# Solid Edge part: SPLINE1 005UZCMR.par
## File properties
Title: Feature: Straight-Sided Splines 8x32x36
Template: Normal.par
Last saved by: Dan
Revision: 8
Application: Solid Edge
Project Name: Piston Pump P52
Mscpartversion: 2
ProtocolId (internal): P00040720102146988
Protocol (internal): P00040720102146988<@PID>[Data]<@EL>P=15{kW<@EL>n=3000{rpm<@EL>Mk=47.747{Nm<@EL>t=0{ND<@EL>Scale=3{ND<@EL>l=27{mm<@EL>z=8{ND<@EL>d=32{mm<@EL>d1=36{mm<@EL>b=6{mm<@EL>f=0.4{mm<@EL>r=0.3{mm<@EL>d_1=30.4{mm<@EL>pom=0{ND<@EL>Mat=User{ND<@EL>Pd=30{MPa<@EL>Ks=0.75{ND<@EL>Pv=14.448{MPa<@EL>lmin=13{mm<@EL>Ready=0{ND<@EL>[Synchronize]<@EL>ChangedVars=<@EL>[Calc]<@EL>CalcName=Spline1<@EL>Optim=1<@EL>WizardMode=2<@EL>[BaseView]<@EL>OnTop=0<@EL>Left=298<@EL>Top=205<@EL>W2=350<@EL>H2=568<@EL>BaseView=1<@EL>EnableUpdate=<@EL>Calculated=1<@EL>InOpt=0<@EL>NewProt=P00040720102146988<@EL>UpdateAll=0<@EL>[View]<@EL>View=MODEL_FM<@EL>Description=Param. feature - shaft<@EL>VISIBLED=1<@EL>Data=(setq _data (list "6x23x26" "8" "32" "36" "0.4" "6" "0.3" "27" "30.4" "0" "0"))<@EL>Driver=C:/PROGRAM FILES/SOLID EDGE V15/HANDBOOK/DATA/DRV/SPLINE1.LSP<@EL>[Files]<@EL>DataFile=SpiData|SPLINE1<@EL>[Object]<@EL>ProtID=<@EL>Description=Straight-Sided Splining Component Wizard<@EL>Object=SPLINE1<@EL>[Main]<@EL>DataFile=SpiData|SPLINE1<@EL>View=MODEL_FM<@EL>Standard=DIN<@EL>PartKey=6x23x26<@EL>[Acad]<@EL>Recalc=0<@EL>SmartPart=1<@EL>Update=0<@EL>ReallySmartPart=1<@EL>Loop=0<@EL>Optim=0<@EL>[Globals]<@EL>Standard=DIN<@EL>Language=CZ<@EL>OldOwnerHwnd=460760<@EL>OwnerHwnd=1115242<@EL>Scale=1.0<@EL>Path=C:\PROGRAM FILES\SOLID EDGE V15\HANDBOOK\DATA\<@EL>TypeOfPart=8<@EL>Unit=mm<@EL>Model=n014942a<@EL>Level=8.00<@EL>RemoveInfo=1.00<@EL>POMPOHL3_FP0=cZ,X:NARYS<@EL>POMPOHL3_FP1=pZ,Z:LEVBOK<@EL>POMPOHL3_FM0=cZ,X:POMPOHL1<@EL>POMPOHL3_FM1=pZ,Z:POMPOHL4<@EL>BOM1=<@EL>BOM2=<@EL>BOM3=<@EL>NormName=Straight-Sided Splines<@EL>Caption=Straight-Sided Splines 8x32x36<@EL>DataType=PART<@EL>OutputVars=Mk,l<@EL>DataChanged=0<@EL>Caption2=Straight-Sided Splines 8x32x36<@EL>RefKey=CALCTP1<@EL>OldModelId=n014942a<@EL>BOM7=1<@EL>BOM5=<@EL>BOM6=<@EL>[Version]<@EL>Version=2.2<@EL>[LOGS]<@EL>4=2004/07/20 12:22:51 PM: ~The Strength Check is OK.~-2147483640~~~txtcheck<@EL>3=~---------------------------------------------------------
Density: 0 kg/mm^3
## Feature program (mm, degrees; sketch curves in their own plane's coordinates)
sketch for "unnamed Protrusion 1" plane through (0, 0, 0) normal (0, 0, 1) x-axis (1, 0, 0)
  circle centre (0, 0) radius 18.18
extrude "unnamed Protrusion 1" add finite 27 along +normal
sketch for "unnamed Hole 1" plane through (0, 0, 0) normal (0, 0, 1) x-axis (1, 0, 0)
  hole centre (0, 0) bore radius 16
hole "unnamed Hole 1" through
sketch for "unnamed Cutout 1" plane through (0, 0, 0) normal (0, 0, 1) x-axis (1, 0, 0)
  line (-3, 17.4112) -> (-3, 15.7162)
  arc centre (0, 0) radius 16 from (3, 15.7162) to (-3, 15.7162) ccw
  line (3, 17.4112) -> (3, 15.7162)
  line (2.6, 17.8112) -> (3, 17.4112)
  arc centre (0, 0) radius 18 from (2.6, 17.8112) to (-2.6, 17.8112) ccw
  line (-3, 17.4112) -> (-2.6, 17.8112)
  dimension (linear) = 3
  dimension (linear) = 2.6
  dimension (linear) = 3
extrude "unnamed Cutout 1" cut through along +normal
sketch for "unnamed Protrusion 2" plane through (0, 0, 0) normal (0, 0, 1) x-axis (1, 0, 0)
  arc centre (-3.8, 15.7162) radius 0.8 from (-3, 15.7162) to (-4.5116, 15.3507) cw
  arc centre (0, 0) radius 16 from (-4.5116, 15.3507) to (-3, 15.7162) cw
extrude "unnamed Protrusion 2" add to key point along +normal
sketch for "unnamed Protrusion 3" plane through (0, 0, 0) normal (0, 0, 1) x-axis (1, 0, 0)
  arc centre (3.8, 15.7162) radius 0.8 from (3, 15.7162) to (4.5116, 15.3507) ccw
  arc centre (0, 0) radius 16 from (3, 15.7162) to (4.5116, 15.3507) cw
extrude "unnamed Protrusion 3" add to key point along +normal
pattern "unnamed Pattern 1" of "unnamed Protrusion 2", "unnamed Cutout 1", "unnamed Protrusion 3"
extrude "unnamed Cutout 2" cut through
extrude "unnamed Protrusion 4" add finite 27
extrude "unnamed Protrusion 5" add finite 27
extrude "unnamed Cutout 3" cut through
extrude "unnamed Protrusion 6" add finite 27
extrude "unnamed Protrusion 7" add finite 27
extrude "unnamed Cutout 4" cut through
extrude "unnamed Protrusion 8" add finite 27
extrude "unnamed Protrusion 9" add finite 27
extrude "unnamed Cutout 5" cut through
extrude "unnamed Protrusion 10" add finite 27
extrude "unnamed Protrusion 11" add finite 27
extrude "unnamed Cutout 6" cut through
extrude "unnamed Protrusion 12" add finite 27
extrude "unnamed Protrusion 13" add finite 27
extrude "unnamed Cutout 7" cut through
extrude "unnamed Protrusion 14" add finite 27
extrude "unnamed Protrusion 15" add finite 27
extrude "unnamed Cutout 8" cut through
extrude "unnamed Protrusion 16" add finite 27
extrude "unnamed Protrusion 17" add finite 27
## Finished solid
Body 1: solid body, 67 faces, 194 edges, 128 vertices.
  Faces by surface: plane 34, cylinder 33
  Edges by curve: line 128, circle 66
Bounding box of the edges (mm): 36.360 x 36.360 x 27.000, from (-18.18, -18.18, 0) to (18.18, 18.18, 27).
Cylindrical faces by radius (mm): R0.8 x16, R16 x8, R18 x8, R18.18 x1
Planar faces by outward normal: +x 4, +y 4, +z 1, -x 4, -y 4, -z 1, oblique 16
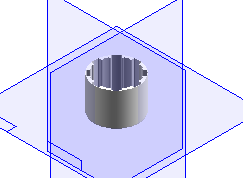
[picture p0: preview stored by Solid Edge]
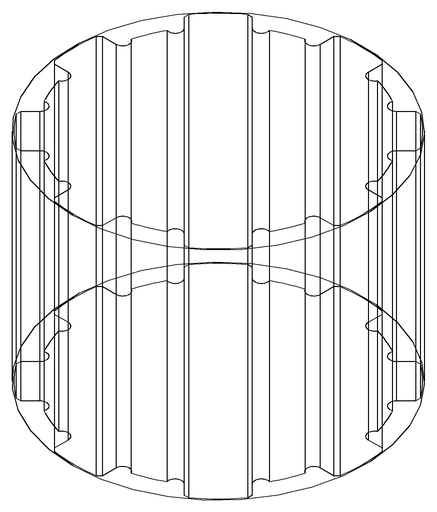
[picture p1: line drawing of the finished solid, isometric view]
